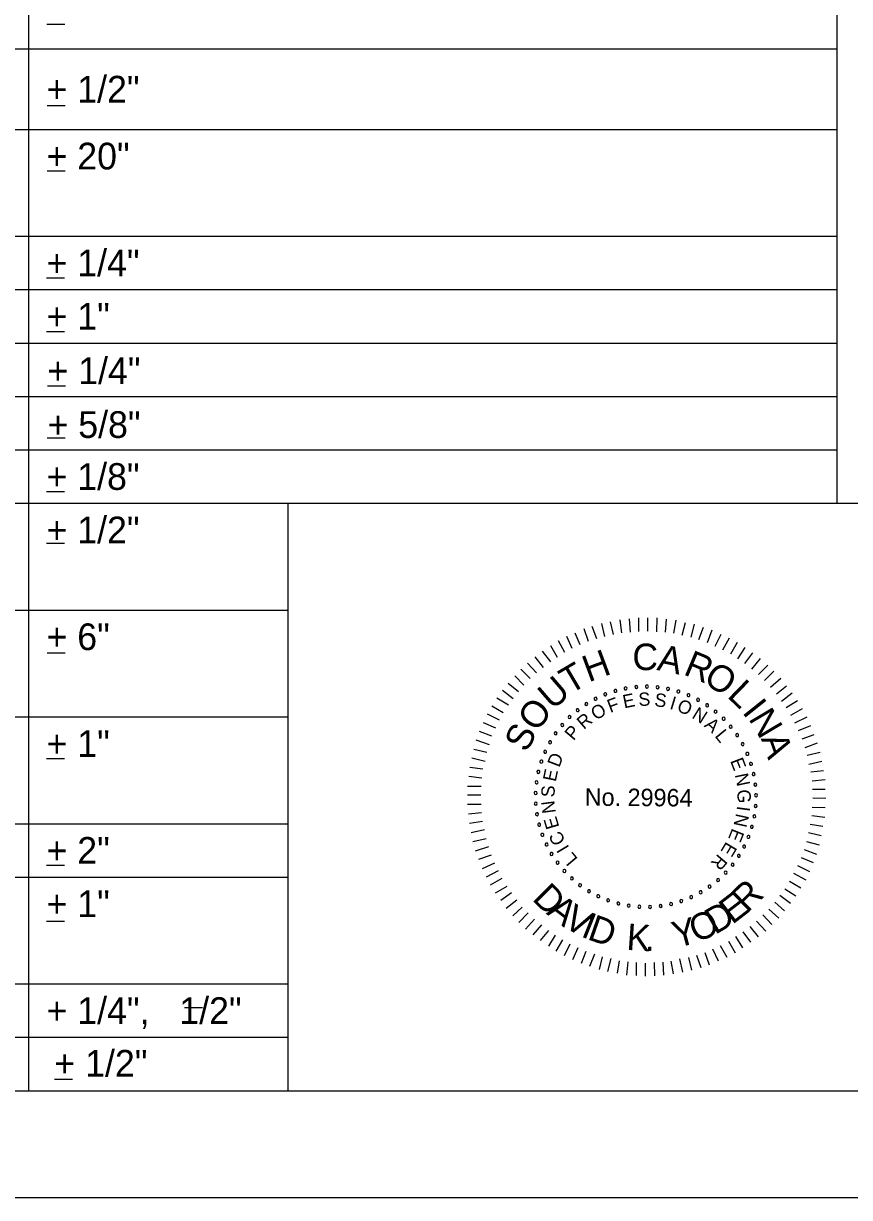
# Model space of a CAD drawing. Extents: x -50.5 to -14.4, y 42.4 to 64.4.
# Drawn here: x -29.12 to -25.26, y 42.45 to 47.94 of the extents above; entities that cross this region are included whole.
import ezdxf

# ---------------------------------------------------------------- set-up
doc = ezdxf.new("R2010")
doc.units = 0
for name, color, linetype in [('BR_BORDER LINES', 7, 'Continuous'), ('BR_TABLE LINES', 7, 'Continuous'), ('BR_TEXT', 7, 'Continuous'), ('Level 31', 7, 'Continuous')]:
    doc.layers.add(name, color=color, linetype=linetype)

msp = doc.modelspace()

# ---------------------------------------------------------------- linework, layer by layer
at = {"layer": 'BR_BORDER LINES'}
for p, q in [((-25.3179, 51.9486), (-25.3179, 45.6987)), ((-27.8847, 45.6987), (-22.5195, 45.6987)), ((-27.8847, 42.9486), (-27.8847, 45.6987)), ((-48.6853, 42.9486), (-15.0192, 42.9486)), ((-33.6075, 42.9486), (-25.3179, 42.9486))]:
    msp.add_line(p, q, dxfattribs=at)
at = {"layer": 'BR_TABLE LINES'}
for p, q in [((-29.1004, 51.9486), (-29.1004, 42.9486)), ((-33.2742, 47.8253), (-25.3179, 47.8253)), ((-33.6075, 47.4486), (-25.3179, 47.4486)), ((-33.6075, 46.9486), (-25.3179, 46.9486)), ((-33.6075, 46.6986), (-25.3179, 46.6986)), ((-33.6075, 46.4486), (-25.3179, 46.4486)), ((-33.6075, 46.1986), (-25.3179, 46.1986)), ((-33.6075, 45.9486), (-25.3179, 45.9486)), ((-33.6075, 45.6986), (-27.8847, 45.6986)), ((-33.6075, 45.1986), (-27.8847, 45.1986)), ((-33.6075, 44.6986), (-27.8847, 44.6986)), ((-33.6075, 44.1986), (-27.8847, 44.1986)), ((-33.6075, 43.9486), (-27.8847, 43.9486)), ((-33.6075, 43.4486), (-27.8847, 43.4486)), ((-33.6075, 43.1986), (-27.8847, 43.1986))]:
    msp.add_line(p, q, dxfattribs=at)
at = {"layer": 'BR_TEXT'}
for p, q in [((-29.0142, 47.9412), (-28.9295, 47.9412)), ((-29.013, 47.5605), (-28.9283, 47.5605)), ((-29.0121, 47.2545), (-28.9274, 47.2545)), ((-29.0153, 46.7544), (-28.9306, 46.7544)), ((-29.0153, 46.5027), (-28.9306, 46.5027)), ((-29.0108, 46.2479), (-28.9261, 46.2479)), ((-29.0121, 46.0042), (-28.9274, 46.0042)), ((-29.0153, 45.7542), (-28.9306, 45.7542)), ((-29.0157, 45.5111), (-28.931, 45.5111)), ((-26.44, 45.0644), (-26.4618, 45.122)), ((-26.4038, 45.0744), (-26.4171, 45.1354)), ((-26.3625, 45.0843), (-26.3767, 45.1437)), ((-26.323, 45.0917), (-26.332, 45.1527)), ((-26.2835, 45.0957), (-26.2873, 45.1567)), ((-26.244, 45.098), (-26.2435, 45.1623)), ((-26.202, 45.1002), (-26.2015, 45.162)), ((-26.1599, 45.0973), (-26.1577, 45.1616)), ((-26.1196, 45.0944), (-26.1148, 45.1552)), ((-26.081, 45.0897), (-26.0702, 45.1506)), ((-26.0408, 45.0817), (-26.0265, 45.1408)), ((-25.9997, 45.071), (-25.9837, 45.1318)), ((-26.5553, 45.0181), (-26.5815, 45.0741)), ((-26.5183, 45.035), (-26.5419, 45.091)), ((-26.4796, 45.0518), (-26.5005, 45.1104)), ((-25.9629, 45.0605), (-25.9409, 45.1177)), ((-25.9235, 45.0472), (-25.9015, 45.1054)), ((-25.8876, 45.0298), (-25.8597, 45.0853)), ((-25.8517, 45.0123), (-25.8203, 45.0678)), ((-26.6252, 44.9767), (-26.6556, 45.031)), ((-26.5898, 45.0004), (-26.6202, 45.0547)), ((-25.8141, 44.994), (-25.7819, 45.0478)), ((-25.7808, 44.9697), (-25.7469, 45.0235)), ((-29.0121, 44.9976), (-28.9274, 44.9976)), ((-26.6899, 44.93), (-26.7299, 44.9801)), ((-26.6562, 44.9555), (-26.6953, 45.0064)), ((-25.7475, 44.948), (-25.711, 44.9983)), ((-25.7151, 44.922), (-25.6744, 44.9714)), ((-26.7522, 44.8782), (-26.7964, 44.9223)), ((-26.7228, 44.9054), (-26.7644, 44.9503)), ((-25.6836, 44.8968), (-25.6403, 44.941)), ((-25.6555, 44.8691), (-25.6122, 44.9125)), ((-26.8068, 44.816), (-26.8562, 44.855)), ((-26.7816, 44.8475), (-26.825, 44.8899)), ((-25.6274, 44.838), (-25.5799, 44.8796)), ((-26.8328, 44.7827), (-26.8822, 44.8226)), ((-25.6002, 44.806), (-25.5536, 44.8442)), ((-25.5765, 44.7723), (-25.5272, 44.8114)), ((-26.8788, 44.717), (-26.9326, 44.7492)), ((-26.8545, 44.7537), (-26.9083, 44.7868)), ((-25.5544, 44.743), (-25.5018, 44.7752)), ((-25.5324, 44.7059), (-25.4789, 44.7372)), ((-26.8963, 44.6828), (-26.9526, 44.7107)), ((-25.5147, 44.6714), (-25.4569, 44.6984)), ((-26.9312, 44.6076), (-26.9894, 44.6295)), ((-26.9137, 44.6461), (-26.971, 44.6714)), ((-25.4969, 44.6344), (-25.4401, 44.6588)), ((-26.9435, 44.5674), (-27.0051, 44.5902)), ((-25.4801, 44.5956), (-25.4233, 44.6166)), ((-25.4667, 44.5552), (-25.409, 44.577)), ((-26.9558, 44.5314), (-27.0167, 44.5465)), ((-25.4567, 44.519), (-25.3965, 44.5331)), ((-29.0153, 44.5039), (-28.9306, 44.5039)), ((-26.9736, 44.4535), (-27.0345, 44.4617)), ((-26.9631, 44.4894), (-27.0256, 44.5054)), ((-25.4485, 44.4769), (-25.3882, 44.4919)), ((-26.9783, 44.4123), (-27.04, 44.4197)), ((-25.4402, 44.4408), (-25.3809, 44.448)), ((-25.4337, 44.3996), (-25.3727, 44.4059)), ((-26.9812, 44.3729), (-27.0455, 44.3734)), ((-25.4323, 44.3601), (-25.3722, 44.3596)), ((-26.9833, 44.3317), (-27.0459, 44.3322)), ((-25.43, 44.3189), (-25.3691, 44.3184)), ((-26.9819, 44.2888), (-27.0462, 44.2876)), ((-26.9796, 44.2501), (-27.0415, 44.2429)), ((-25.433, 44.276), (-25.3729, 44.2738)), ((-26.9757, 44.2089), (-27.0367, 44.2)), ((-25.4422, 44.1963), (-25.3831, 44.1863)), ((-25.435, 44.2374), (-25.3741, 44.2292)), ((-26.9657, 44.1693), (-27.0284, 44.1561)), ((-25.4511, 44.1568), (-25.3911, 44.1426)), ((-26.9592, 44.1272), (-27.0202, 44.1131)), ((-26.9475, 44.0903), (-27.0094, 44.0693)), ((-25.4706, 44.0781), (-25.4133, 44.0561)), ((-25.46, 44.1148), (-25.4001, 44.0998)), ((-26.9358, 44.0515), (-26.9943, 44.0306)), ((-25.4847, 44.0396), (-25.4282, 44.0176)), ((-29.0153, 44.0038), (-28.9306, 44.0038)), ((-26.9189, 44.0145), (-26.9766, 43.9875)), ((-26.9021, 43.9783), (-26.9589, 43.9487)), ((-25.5205, 43.9669), (-25.4632, 43.9364)), ((-25.5022, 44.0028), (-25.4457, 43.9749)), ((-26.8852, 43.9413), (-26.9395, 43.91)), ((-25.5388, 43.9301), (-25.4859, 43.898)), ((-26.8615, 43.9042), (-26.9158, 43.8729)), ((-26.8403, 43.8748), (-26.8903, 43.8383)), ((-25.584, 43.8644), (-25.5353, 43.8271)), ((-25.5614, 43.8934), (-25.5093, 43.8612)), ((-26.8148, 43.8411), (-26.8649, 43.8021)), ((-26.7902, 43.8075), (-26.8343, 43.7666)), ((-25.6083, 43.8312), (-25.5623, 43.7913)), ((-26.7612, 43.7815), (-26.8062, 43.7364)), ((-26.7323, 43.7512), (-26.7747, 43.7052)), ((-25.6645, 43.7724), (-25.622, 43.7266)), ((-25.636, 43.7979), (-25.5891, 43.7563)), ((-29.0153, 43.7425), (-28.9306, 43.7425)), ((-26.6999, 43.7252), (-26.7406, 43.6783)), ((-26.6666, 43.6992), (-26.7065, 43.6514)), ((-25.7579, 43.6917), (-25.7222, 43.6433)), ((-25.7251, 43.7172), (-25.6851, 43.6696)), ((-25.6931, 43.7426), (-25.6506, 43.6959)), ((-26.6359, 43.6774), (-26.6672, 43.6254)), ((-26.6009, 43.6549), (-26.6322, 43.6011)), ((-25.8252, 43.6485), (-25.7939, 43.5941)), ((-25.7915, 43.6705), (-25.7585, 43.6179)), ((-26.5668, 43.6348), (-26.5938, 43.5793)), ((-26.53, 43.6174), (-26.5545, 43.5618)), ((-26.4915, 43.5999), (-26.5134, 43.5434)), ((-26.4522, 43.5876), (-26.475, 43.5294)), ((-25.9751, 43.5836), (-25.9541, 43.5251)), ((-25.9355, 43.5953), (-25.9145, 43.5385)), ((-25.8993, 43.6122), (-25.8723, 43.5562)), ((-25.8631, 43.629), (-25.8327, 43.573)), ((-26.4162, 43.5752), (-26.4304, 43.5162)), ((-26.3751, 43.568), (-26.3902, 43.5064)), ((-26.3357, 43.5565), (-26.3456, 43.4983)), ((-26.2963, 43.552), (-26.3011, 43.4902)), ((-26.2568, 43.549), (-26.2573, 43.4872)), ((-26.2148, 43.5461), (-26.2153, 43.4852)), ((-26.1727, 43.5484), (-26.1715, 43.4865)), ((-26.1324, 43.5506), (-26.1286, 43.4888)), ((-26.0937, 43.5545), (-26.0839, 43.4961)), ((-26.0533, 43.5654), (-26.0401, 43.5035)), ((-26.0121, 43.5719), (-25.9971, 43.5126)), ((-28.3706, 43.3375), (-28.2859, 43.3375)), ((-28.9784, 43.0027), (-28.8937, 43.0027))]:
    msp.add_line(p, q, dxfattribs=at)
for centre, start, end in [((-26.256, 44.8383), 5.0653, 185.0653), ((-26.2062, 44.8402), 359.5268, 179.5268), ((-26.4465, 44.7836), 27.2191, 207.2191), ((-26.4011, 44.8042), 21.6807, 201.6807), ((-26.4011, 44.8042), 201.6807, 21.6807), ((-26.3539, 44.8202), 16.1422, 196.1422), ((-26.3539, 44.8202), 196.1422, 16.1422), ((-26.3054, 44.8316), 10.6038, 190.6038), ((-26.3054, 44.8316), 190.6038, 10.6038), ((-26.256, 44.8383), 185.0653, 5.0653), ((-26.2062, 44.8402), 179.5268, 359.5268), ((-26.1565, 44.8373), 353.9884, 173.9884), ((-26.1565, 44.8373), 173.9884, 353.9884), ((-26.1073, 44.8296), 168.4499, 348.4499), ((-26.1073, 44.8296), 348.4499, 168.4499), ((-26.059, 44.8172), 162.9114, 342.9114), ((-26.059, 44.8172), 342.9114, 162.9114), ((-26.0122, 44.8002), 157.373, 337.373), ((-26.0122, 44.8002), 337.373, 157.373), ((-26.5303, 44.7299), 38.2961, 218.2961), ((-26.4897, 44.7588), 32.7576, 212.7576), ((-26.4897, 44.7588), 212.7576, 32.7576), ((-26.4465, 44.7836), 207.2191, 27.2191), ((-25.9672, 44.7787), 151.8345, 331.8345), ((-25.9672, 44.7787), 331.8345, 151.8345), ((-25.9245, 44.753), 146.2961, 326.2961), ((-25.9245, 44.753), 326.2961, 146.2961), ((-26.568, 44.6973), 43.8345, 223.8345), ((-26.568, 44.6973), 223.8345, 43.8345), ((-26.5303, 44.7299), 218.2961, 38.2961), ((-25.8845, 44.7233), 140.7576, 320.7576), ((-25.8845, 44.7233), 320.7576, 140.7576), ((-25.8475, 44.6899), 135.2191, 315.2191), ((-25.8475, 44.6899), 315.2191, 135.2191), ((-26.6329, 44.6218), 54.9114, 234.9114), ((-26.6329, 44.6218), 234.9114, 54.9114), ((-26.6023, 44.6611), 49.373, 229.373), ((-26.6023, 44.6611), 229.373, 49.373), ((-25.814, 44.6531), 129.6807, 309.6807), ((-25.814, 44.6531), 309.6807, 129.6807), ((-26.6596, 44.5798), 60.4499, 240.4499), ((-26.6596, 44.5798), 240.4499, 60.4499), ((-25.7841, 44.6132), 124.1422, 304.1422), ((-25.7841, 44.6132), 304.1422, 124.1422), ((-25.7583, 44.5706), 118.6038, 298.6038), ((-25.7583, 44.5706), 298.6038, 118.6038), ((-26.6822, 44.5354), 65.9884, 245.9884), ((-26.6822, 44.5354), 245.9884, 65.9884), ((-25.7366, 44.5257), 113.0653, 293.0653), ((-25.7366, 44.5257), 293.0653, 113.0653), ((-26.7003, 44.4889), 71.5268, 251.5268), ((-26.7003, 44.4889), 251.5268, 71.5268), ((-25.7195, 44.4789), 107.5268, 287.5268), ((-25.7195, 44.4789), 287.5268, 107.5268), ((-26.7139, 44.441), 77.0653, 257.0653), ((-26.7139, 44.441), 257.0653, 77.0653), ((-25.7069, 44.4307), 101.9884, 281.9884), ((-25.7069, 44.4307), 281.9884, 101.9884), ((-26.7228, 44.392), 82.6038, 262.6038), ((-26.7228, 44.392), 262.6038, 82.6038), ((-25.699, 44.3815), 96.4499, 276.4499), ((-25.699, 44.3815), 276.4499, 96.4499), ((-26.7269, 44.3423), 88.1422, 268.1422), ((-26.7262, 44.2925), 93.6807, 273.6807), ((-26.7269, 44.3423), 268.1422, 88.1422), ((-26.7262, 44.2925), 273.6807, 93.6807), ((-25.6959, 44.3317), 90.9114, 270.9114), ((-25.6959, 44.3317), 270.9114, 90.9114), ((-26.7207, 44.243), 99.2191, 279.2191), ((-26.7207, 44.243), 279.2191, 99.2191), ((-25.6976, 44.2819), 85.373, 265.373), ((-25.6976, 44.2819), 265.373, 85.373), ((-26.7105, 44.1942), 104.7576, 284.7576), ((-26.7105, 44.1942), 284.7576, 104.7576), ((-25.7154, 44.184), 74.2961, 254.2961), ((-25.7154, 44.184), 254.2961, 74.2961), ((-25.7041, 44.2325), 79.8345, 259.8345), ((-25.7041, 44.2325), 259.8345, 79.8345), ((-26.6956, 44.1466), 110.2961, 290.2961), ((-26.6956, 44.1466), 290.2961, 110.2961), ((-25.7312, 44.1368), 68.7576, 248.7576), ((-25.7312, 44.1368), 248.7576, 68.7576), ((-26.6761, 44.1008), 115.8345, 295.8345), ((-26.6761, 44.1008), 295.8345, 115.8345), ((-25.7516, 44.0913), 63.2191, 243.2191), ((-25.7516, 44.0913), 243.2191, 63.2191), ((-26.6524, 44.057), 121.373, 301.373), ((-26.6524, 44.057), 301.373, 121.373), ((-26.6245, 44.0157), 126.9114, 306.9114), ((-26.6245, 44.0157), 306.9114, 126.9114), ((-25.7763, 44.048), 57.6807, 237.6807), ((-25.7763, 44.048), 237.6807, 57.6807), ((-26.5927, 43.9773), 132.4499, 312.4499), ((-26.5927, 43.9773), 312.4499, 132.4499), ((-25.8375, 43.9695), 46.6038, 226.6038), ((-25.8375, 43.9695), 226.6038, 46.6038), ((-25.805, 44.0073), 52.1422, 232.1422), ((-25.805, 44.0073), 232.1422, 52.1422), ((-26.5574, 43.9421), 137.9884, 317.9884), ((-26.5574, 43.9421), 317.9884, 137.9884), ((-26.5189, 43.9105), 143.5268, 323.5268), ((-26.5189, 43.9105), 323.5268, 143.5268), ((-25.9127, 43.9043), 35.5268, 215.5268), ((-25.8735, 43.9351), 41.0653, 221.0653), ((-25.8735, 43.9351), 221.0653, 41.0653), ((-26.4775, 43.8827), 149.0653, 329.0653), ((-26.4775, 43.8827), 329.0653, 149.0653), ((-26.4336, 43.8591), 154.6038, 334.6038), ((-26.4336, 43.8591), 334.6038, 154.6038), ((-25.999, 43.8547), 24.4499, 204.4499), ((-25.999, 43.8547), 204.4499, 24.4499), ((-25.9547, 43.8774), 29.9884, 209.9884), ((-25.9547, 43.8774), 209.9884, 29.9884), ((-25.9127, 43.9043), 215.5268, 35.5268), ((-26.3877, 43.8399), 160.1422, 340.1422), ((-26.3877, 43.8399), 340.1422, 160.1422), ((-26.3401, 43.8251), 165.6807, 345.6807), ((-26.3401, 43.8251), 345.6807, 165.6807), ((-26.2913, 43.8151), 171.2191, 351.2191), ((-26.2913, 43.8151), 351.2191, 171.2191), ((-26.2417, 43.8097), 356.7576, 176.7576), ((-26.2417, 43.8097), 176.7576, 356.7576), ((-26.1919, 43.8092), 2.2961, 182.2961), ((-26.1919, 43.8092), 182.2961, 2.2961), ((-26.1422, 43.8135), 7.8345, 187.8345), ((-26.1422, 43.8135), 187.8345, 7.8345), ((-26.0932, 43.8226), 13.373, 193.373), ((-26.0932, 43.8226), 193.373, 13.373), ((-26.0454, 43.8364), 18.9114, 198.9114), ((-26.0454, 43.8364), 198.9114, 18.9114)]:
    msp.add_arc(centre, 0.00701, start, end, dxfattribs=at)
at = {"layer": 'Level 31'}
msp.add_lwpolyline([(-50.5186, 42.4486), (-14.5186, 42.4486), (-14.5186, 64.4486), (-50.5186, 64.4486)], close=True, dxfattribs=at)

# ---------------------------------------------------------------- texts
at = {"layer": 'BR_TEXT'}
for s, p in [('+ 1/2"', (-29.0157, 47.5742)), ('+ 20"', (-29.0157, 47.2611)), ('+ 1/4"', (-29.0157, 46.7611)), ('+ 1"', (-29.0157, 46.5111)), ('+ 1/4"', (-29.0112, 46.2564)), ('+ 5/8"', (-29.011, 46.0042)), ('+ 1/8"', (-29.0157, 45.7611)), ('+ 1/2"', (-29.0157, 45.5111)), ('+ 6"', (-29.0157, 45.0111)), ('+ 1"', (-29.0157, 44.5111)), ('+ 2"', (-29.0157, 44.0111)), ('+ 1"', (-29.0157, 43.7611)), ('+ 1/4",   1/2"', (-29.0157, 43.2611)), ('+ 1/2"', (-28.9788, 43.0145))]:
    msp.add_text(s, height=0.125, dxfattribs=at).set_placement(p)
for s, height, rotation, p in [('H', 0.1241, 20.3637, (-26.4791, 44.8595)), ('C', 0.1241, 359.5482, (-26.2747, 44.9178)), ('A', 0.1241, 348.1981, (-26.1633, 44.9186)), ('T', 0.1241, 30.4992, (-26.567, 44.802)), ('R', 0.1241, 337.4344, (-26.0401, 44.8987)), ('O', 0.1239, 326.5869, (-25.9478, 44.862)), ('U', 0.1241, 40.8022, (-26.6482, 44.7272)), ('L', 0.1241, 315.9488, (-25.8352, 44.7942)), ('F', 0.0622, 20.6127, (-26.3779, 44.7166)), ('E', 0.0622, 11.4103, (-26.3127, 44.7383)), ('S', 0.0622, 2.208, (-26.2449, 44.7493)), ('S', 0.0622, 352.6608, (-26.1736, 44.7491)), ('I', 0.0622, 343.1136, (-26.1034, 44.7371)), ('O', 0.1241, 52.0267, (-26.7228, 44.6233)), ('O', 0.0622, 30.8477, (-26.4452, 44.6806)), ('O', 0.0622, 338.4392, (-26.07, 44.727)), ('N', 0.0622, 328.2042, (-26.0003, 44.6955)), ('I', 0.1241, 308.6613, (-25.7639, 44.7199)), ('N', 0.1241, 300.7037, (-25.7333, 44.6905)), ('R', 0.0622, 40.3949, (-26.5014, 44.6367)), ('A', 0.0622, 318.657, (-25.9414, 44.6555)), ('S', 0.1239, 63.2511, (-26.7681, 44.5277)), ('P', 0.0622, 49.9421, (-26.5495, 44.5841)), ('L', 0.0622, 309.4546, (-25.8916, 44.6082)), ('A', 0.1241, 289.4792, (-25.6741, 44.5975)), ('D', 0.0622, 69.0364, (-26.6164, 44.4589)), ('E', 0.0622, 291.049, (-25.8177, 44.4929)), ('E', 0.0622, 78.2388, (-26.633, 44.3922)), ('N', 0.0622, 281.8466, (-25.7955, 44.4279)), ('S', 0.0622, 87.786, (-26.6387, 44.3212)), ('No. 29964', 0.08175, 359.5268, (-26.4976, 44.2828)), ('G', 0.0622, 272.2995, (-25.7838, 44.3576)), ('N', 0.0622, 97.3332, (-26.6325, 44.2502)), ('N', 0.0622, 257.7339, (-25.7887, 44.2491)), ('I', 0.0622, 262.4084, (-25.7841, 44.2837)), ('E', 0.0622, 106.5355, (-26.6155, 44.1836)), ('C', 0.0622, 116.4266, (-26.5857, 44.1161)), ('E', 0.0622, 248.1867, (-25.8067, 44.1802)), ('I', 0.0622, 121.1011, (-26.5676, 44.0862)), ('E', 0.0622, 238.9844, (-25.8347, 44.1174)), ('L', 0.0622, 129.9595, (-26.5269, 44.034)), ('R', 0.0622, 229.782, (-25.8723, 44.0599)), ('D', 0.1236, 315.4053, (-26.7474, 43.8434)), ('R', 0.1236, 44.5947, (-25.7366, 43.7779)), ('E', 0.1236, 37.5339, (-25.8072, 43.724)), ('A', 0.1236, 322.8377, (-26.6808, 43.7778)), ('V', 0.1236, 330.5179, (-26.6037, 43.7196)), ('D', 0.1236, 30.1015, (-25.8881, 43.6771)), ('I', 0.1236, 338.1981, (-26.5195, 43.6722)), ('D', 0.1236, 340.7995, (-26.4896, 43.6588)), ('Y', 0.1236, 14.8649, (-26.0692, 43.6155)), ('O', 0.1236, 22.4212, (-25.9773, 43.64)), ('K', 0.1236, 356.098, (-26.3043, 43.6082)), ('.', 0.1236, 3.1588, (-26.2157, 43.6019))]:
    msp.add_text(s, height=height, rotation=rotation, dxfattribs=at).set_placement(p)

doc.saveas('drawing.dxf')
